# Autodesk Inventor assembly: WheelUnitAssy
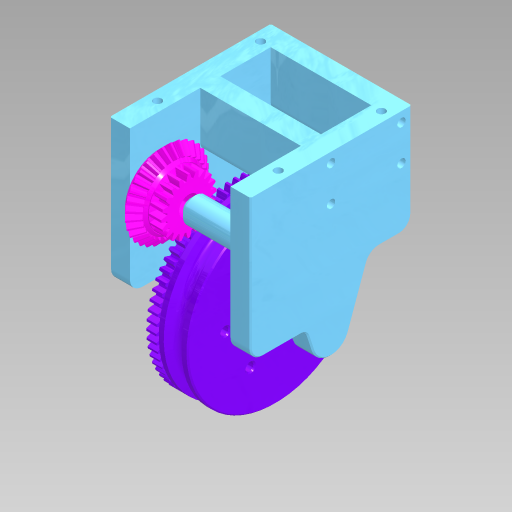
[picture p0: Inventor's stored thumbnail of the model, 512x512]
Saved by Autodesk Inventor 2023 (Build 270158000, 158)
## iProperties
Created: 2024-05
Part Number: WheelUnitAssy
Document SubType Name: Assembly
Designer: kumagai
Author: kumagai
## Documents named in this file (6)
- X:\Develop\CAD\NakataOmni\DriveUnitR3\WheelUnitAssy.iam
- X:\Develop\CAD\NakataOmni\DriveUnitR3\WheelFrameAB\WheelFrameAB-AB.ipt
- X:\Develop\CAD\NakataOmni\DriveUnitR3\WheelFrameAB.ipt
- X:\Develop\CAD\NakataOmni\DriveUnitR3\Wheel.ipt
- X:\Develop\CAD\NakataOmni\DriveUnitR3\WheelGear.ipt
- X:\Develop\CAD\NakataOmni\DriveUnitR3\BevelFinalGear_c.ipt
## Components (4 placed, 4 different names)
1. WheelFrameAB-AB:1 — メイト:4, メイト:5, メイト:6, メイト:7
2. Wheel:1 — メイト:1, メイト:2, メイト:3, メイト:4
3. 平歯車1:1 — メイト:1, メイト:2, メイト:3, メイト:5
4. BevelFinalGear_c:1 — メイト:6, メイト:7
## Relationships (7: Mate 7)
- メイト:1 [Mate]: Wheel:1 ↔ 平歯車1:1
- メイト:2 [Mate]: Wheel:1 ↔ 平歯車1:1
- メイト:3 [Mate]: Wheel:1 ↔ 平歯車1:1
- メイト:4 [Mate]: WheelFrameAB-AB:1 ↔ Wheel:1
- メイト:5 [Mate]: WheelFrameAB-AB:1 ↔ 平歯車1:1
- メイト:6 [Mate]: WheelFrameAB-AB:1 ↔ BevelFinalGear_c:1
- メイト:7 [Mate]: WheelFrameAB-AB:1 ↔ BevelFinalGear_c:1
